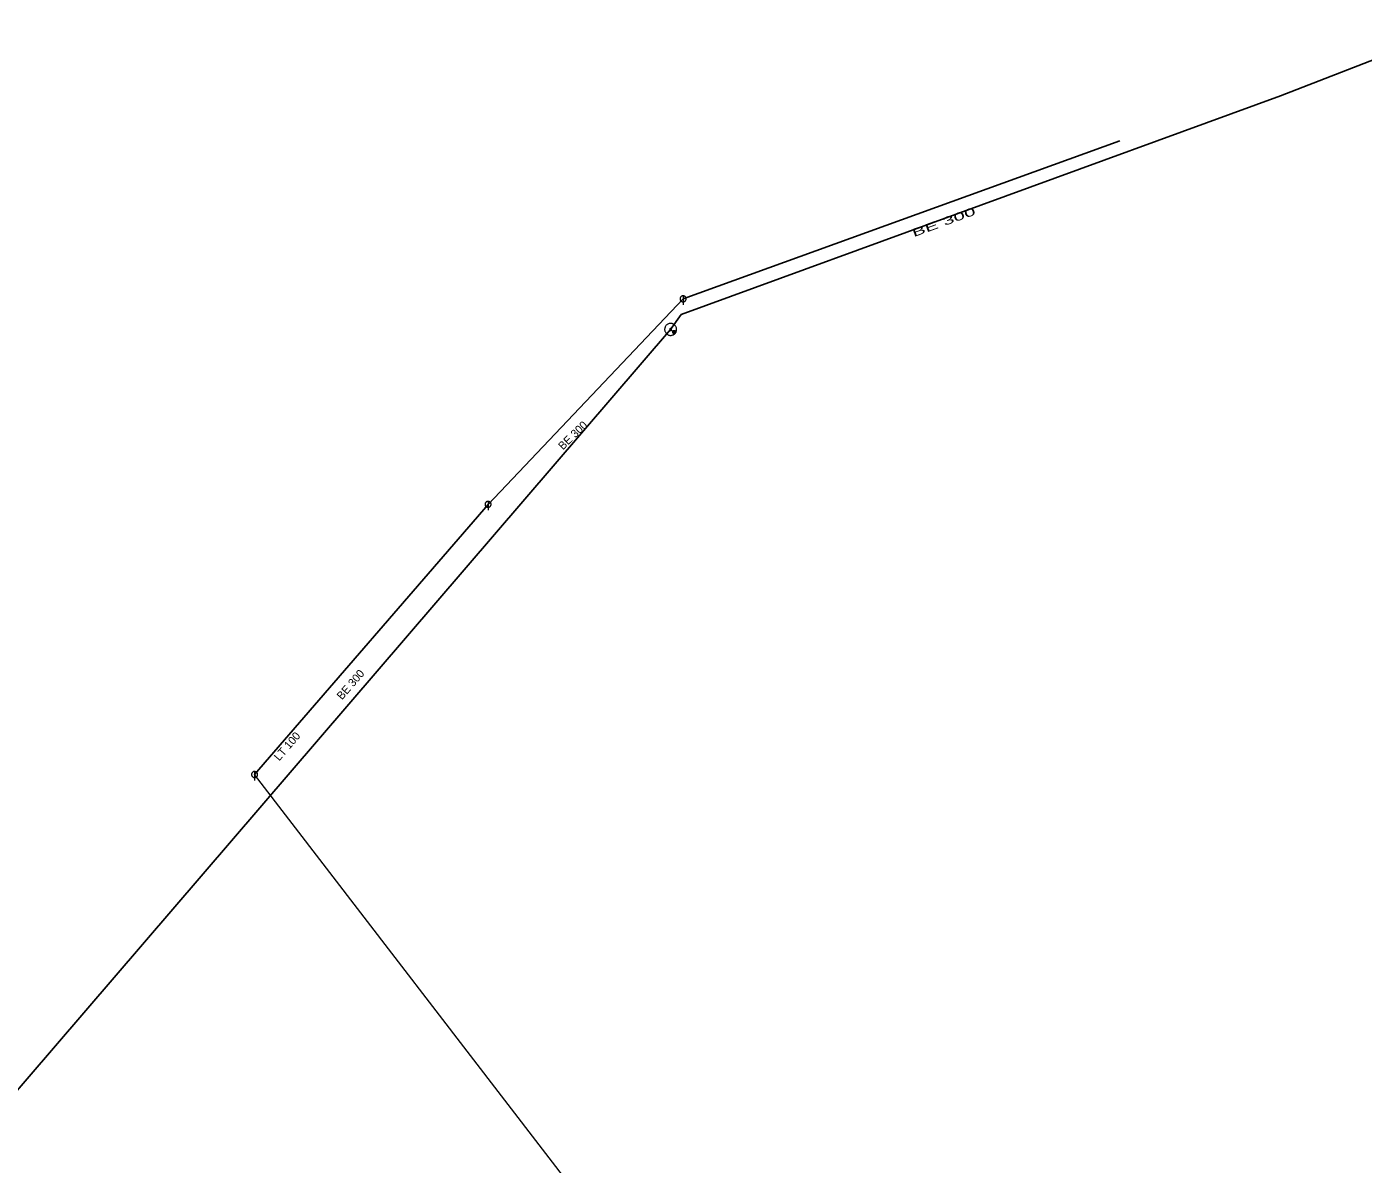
# Model space of a CAD drawing. Extents: x -687515 to -686506, y -974029 to -973461.
# Drawn here: x -687277.4 to -687166.1, y -973560 to -973465.2 of the extents above; entities that cross this region are included whole.
import ezdxf
from ezdxf.enums import TextEntityAlignment as Align

# ---------------------------------------------------------------- set-up
doc = ezdxf.new("R2010")
doc.units = 0
doc.header["$LTSCALE"] = 0.27
for name, color, linetype, lineweight in [('1', 7, 'Continuous', 13), ('11', 7, 'Continuous', 13), ('14', 7, 'Continuous', 25), ('17', 7, 'Continuous', 25), ('22', 7, 'Continuous', 13), ('47', 7, 'Continuous', 13), ('9', 7, 'Continuous', 13)]:
    doc.layers.add(name, color=color, linetype=linetype, lineweight=lineweight)

msp = doc.modelspace()

# ---------------------------------------------------------------- linework, layer by layer
at = {"layer": '11'}
msp.add_line((-687229.217, -973565.501), (-687258.444, -973527.487), dxfattribs=at)
at = {"layer": '14'}
msp.add_line((-687222.741, -973487.844), (-687186.354, -973474.678), dxfattribs=at)
at = {"layer": '14', "lineweight": 13}
msp.add_line((-687223.779, -973490.391), (-687223.489, -973490.623), dxfattribs=at)
at = {"layer": '14'}
msp.add_lwpolyline([(-687258.444, -973527.487), (-687238.992, -973504.972), (-687222.741, -973487.844)], dxfattribs=at)
at = {"layer": '17'}
msp.add_line((-687223.779, -973490.391), (-687283.189, -973559.579), dxfattribs=at)
msp.add_lwpolyline([(-687157.299, -973465.166), (-687162.314, -973466.789), (-687172.973, -973470.914), (-687222.892, -973489.136), (-687223.779, -973490.391)], dxfattribs=at)
at = {"layer": '22'}
for p, q in [((-687222.74, -973487.592), (-687222.741, -973488.336)), ((-687238.991, -973504.72), (-687238.992, -973505.463)), ((-687258.443, -973527.235), (-687258.444, -973527.978))]:
    msp.add_line(p, q, dxfattribs=at)
for points in [[(-687222.489, -973487.844), (-687222.49, -973487.818), (-687222.494, -973487.792), (-687222.5, -973487.766), (-687222.51, -973487.742), (-687222.522, -973487.718), (-687222.536, -973487.696), (-687222.553, -973487.675), (-687222.571, -973487.657), (-687222.592, -973487.64), (-687222.614, -973487.626), (-687222.638, -973487.614), (-687222.662, -973487.604), (-687222.688, -973487.598), (-687222.714, -973487.594), (-687222.74, -973487.592), (-687222.766, -973487.593), (-687222.792, -973487.597), (-687222.818, -973487.603), (-687222.843, -973487.613), (-687222.866, -973487.625), (-687222.888, -973487.639), (-687222.909, -973487.656), (-687222.927, -973487.674), (-687222.944, -973487.695), (-687222.958, -973487.717), (-687222.97, -973487.741), (-687222.98, -973487.765), (-687222.987, -973487.791), (-687222.991, -973487.817), (-687222.993, -973487.843), (-687222.992, -973487.869), (-687222.988, -973487.895), (-687222.981, -973487.921), (-687222.971, -973487.946), (-687222.959, -973487.969), (-687222.945, -973487.991), (-687222.928, -973488.012), (-687222.91, -973488.03), (-687222.889, -973488.047), (-687222.867, -973488.061), (-687222.844, -973488.073), (-687222.819, -973488.083), (-687222.793, -973488.09), (-687222.767, -973488.094), (-687222.741, -973488.096), (-687222.715, -973488.095), (-687222.689, -973488.091), (-687222.663, -973488.084), (-687222.639, -973488.074), (-687222.615, -973488.062), (-687222.593, -973488.048), (-687222.572, -973488.031), (-687222.554, -973488.013), (-687222.537, -973487.992), (-687222.523, -973487.97), (-687222.511, -973487.947), (-687222.501, -973487.922), (-687222.495, -973487.896), (-687222.491, -973487.87)], [(-687238.74, -973504.972), (-687238.741, -973504.946), (-687238.745, -973504.92), (-687238.751, -973504.894), (-687238.761, -973504.87), (-687238.773, -973504.846), (-687238.787, -973504.824), (-687238.804, -973504.803), (-687238.822, -973504.785), (-687238.843, -973504.768), (-687238.865, -973504.754), (-687238.889, -973504.742), (-687238.913, -973504.732), (-687238.939, -973504.726), (-687238.965, -973504.722), (-687238.991, -973504.72), (-687239.017, -973504.721), (-687239.043, -973504.725), (-687239.069, -973504.731), (-687239.094, -973504.741), (-687239.117, -973504.753), (-687239.139, -973504.767), (-687239.16, -973504.784), (-687239.178, -973504.802), (-687239.195, -973504.823), (-687239.209, -973504.845), (-687239.221, -973504.869), (-687239.231, -973504.893), (-687239.238, -973504.919), (-687239.242, -973504.945), (-687239.244, -973504.971), (-687239.243, -973504.997), (-687239.239, -973505.023), (-687239.232, -973505.049), (-687239.222, -973505.074), (-687239.21, -973505.097), (-687239.196, -973505.119), (-687239.179, -973505.14), (-687239.161, -973505.158), (-687239.14, -973505.175), (-687239.118, -973505.189), (-687239.095, -973505.201), (-687239.07, -973505.211), (-687239.044, -973505.218), (-687239.018, -973505.222), (-687238.992, -973505.223), (-687238.966, -973505.223), (-687238.94, -973505.219), (-687238.914, -973505.212), (-687238.89, -973505.202), (-687238.866, -973505.19), (-687238.844, -973505.176), (-687238.823, -973505.159), (-687238.805, -973505.141), (-687238.788, -973505.12), (-687238.774, -973505.098), (-687238.762, -973505.075), (-687238.752, -973505.05), (-687238.746, -973505.024), (-687238.742, -973504.998)], [(-687258.192, -973527.487), (-687258.193, -973527.461), (-687258.197, -973527.435), (-687258.203, -973527.409), (-687258.213, -973527.385), (-687258.225, -973527.361), (-687258.239, -973527.339), (-687258.256, -973527.318), (-687258.274, -973527.3), (-687258.295, -973527.283), (-687258.317, -973527.269), (-687258.341, -973527.257), (-687258.365, -973527.247), (-687258.391, -973527.241), (-687258.417, -973527.237), (-687258.443, -973527.235), (-687258.469, -973527.236), (-687258.495, -973527.24), (-687258.521, -973527.246), (-687258.546, -973527.256), (-687258.569, -973527.268), (-687258.591, -973527.282), (-687258.612, -973527.299), (-687258.63, -973527.317), (-687258.647, -973527.338), (-687258.661, -973527.36), (-687258.673, -973527.384), (-687258.683, -973527.408), (-687258.69, -973527.434), (-687258.694, -973527.46), (-687258.696, -973527.486), (-687258.695, -973527.512), (-687258.691, -973527.538), (-687258.684, -973527.564), (-687258.674, -973527.589), (-687258.662, -973527.612), (-687258.648, -973527.634), (-687258.631, -973527.655), (-687258.613, -973527.673), (-687258.592, -973527.69), (-687258.57, -973527.704), (-687258.547, -973527.716), (-687258.522, -973527.726), (-687258.496, -973527.733), (-687258.47, -973527.737), (-687258.444, -973527.739), (-687258.418, -973527.738), (-687258.392, -973527.734), (-687258.366, -973527.727), (-687258.342, -973527.717), (-687258.318, -973527.705), (-687258.296, -973527.691), (-687258.275, -973527.674), (-687258.257, -973527.656), (-687258.24, -973527.635), (-687258.226, -973527.613), (-687258.214, -973527.59), (-687258.204, -973527.565), (-687258.198, -973527.539), (-687258.194, -973527.513)]]:
    msp.add_lwpolyline(points, close=True, dxfattribs=at)
at = {"layer": '47'}
for points in [[(-687223.47, -973489.997), (-687223.513, -973489.967), (-687223.559, -973489.942), (-687223.607, -973489.922), (-687223.656, -973489.906), (-687223.708, -973489.895), (-687223.761, -973489.891), (-687223.812, -973489.892), (-687223.864, -973489.899), (-687223.915, -973489.91), (-687223.965, -973489.927), (-687224.013, -973489.949), (-687224.057, -973489.976), (-687224.099, -973490.007), (-687224.138, -973490.043), (-687224.172, -973490.082), (-687224.202, -973490.125), (-687224.227, -973490.171), (-687224.248, -973490.219), (-687224.263, -973490.268), (-687224.274, -973490.32), (-687224.278, -973490.373), (-687224.277, -973490.425), (-687224.271, -973490.477), (-687224.26, -973490.528), (-687224.242, -973490.577), (-687224.22, -973490.625), (-687224.193, -973490.67), (-687224.162, -973490.711), (-687224.126, -973490.75), (-687224.087, -973490.784), (-687224.044, -973490.814), (-687223.998, -973490.839), (-687223.95, -973490.861), (-687223.901, -973490.875), (-687223.849, -973490.886), (-687223.797, -973490.891), (-687223.744, -973490.89), (-687223.692, -973490.884), (-687223.641, -973490.872), (-687223.592, -973490.854), (-687223.544, -973490.832), (-687223.5, -973490.806), (-687223.458, -973490.774), (-687223.419, -973490.738), (-687223.385, -973490.699), (-687223.355, -973490.656), (-687223.33, -973490.61), (-687223.309, -973490.563), (-687223.294, -973490.513), (-687223.283, -973490.461), (-687223.278, -973490.409), (-687223.28, -973490.357), (-687223.286, -973490.305), (-687223.298, -973490.254), (-687223.315, -973490.204), (-687223.337, -973490.156), (-687223.363, -973490.112), (-687223.395, -973490.07), (-687223.431, -973490.031)], [(-687223.728, -973490.326), (-687223.735, -973490.32), (-687223.743, -973490.317), (-687223.75, -973490.314), (-687223.758, -973490.311), (-687223.767, -973490.309), (-687223.776, -973490.309), (-687223.784, -973490.309), (-687223.793, -973490.31), (-687223.801, -973490.312), (-687223.809, -973490.314), (-687223.817, -973490.318), (-687223.824, -973490.323), (-687223.831, -973490.328), (-687223.837, -973490.333), (-687223.843, -973490.34), (-687223.849, -973490.347), (-687223.852, -973490.355), (-687223.855, -973490.362), (-687223.858, -973490.37), (-687223.86, -973490.379), (-687223.86, -973490.388), (-687223.86, -973490.396), (-687223.859, -973490.405), (-687223.858, -973490.414), (-687223.855, -973490.421), (-687223.851, -973490.429), (-687223.846, -973490.436), (-687223.841, -973490.443), (-687223.836, -973490.449), (-687223.829, -973490.455), (-687223.822, -973490.461), (-687223.814, -973490.464), (-687223.807, -973490.467), (-687223.799, -973490.47), (-687223.79, -973490.472), (-687223.782, -973490.473), (-687223.773, -973490.472), (-687223.764, -973490.471), (-687223.755, -973490.47), (-687223.748, -973490.467), (-687223.74, -973490.463), (-687223.733, -973490.458), (-687223.726, -973490.453), (-687223.72, -973490.448), (-687223.714, -973490.441), (-687223.708, -973490.434), (-687223.705, -973490.426), (-687223.702, -973490.419), (-687223.699, -973490.411), (-687223.697, -973490.402), (-687223.696, -973490.394), (-687223.697, -973490.385), (-687223.698, -973490.376), (-687223.7, -973490.368), (-687223.702, -973490.36), (-687223.706, -973490.352), (-687223.711, -973490.345), (-687223.716, -973490.338), (-687223.721, -973490.332)]]:
    msp.add_lwpolyline(points, close=True, dxfattribs=at)
at = {"layer": '9'}
for points in [[(-687223.362, -973490.623), (-687223.364, -973490.61), (-687223.365, -973490.597), (-687223.369, -973490.584), (-687223.374, -973490.572), (-687223.379, -973490.56), (-687223.387, -973490.549), (-687223.394, -973490.539), (-687223.404, -973490.529), (-687223.414, -973490.521), (-687223.426, -973490.514), (-687223.438, -973490.508), (-687223.45, -973490.503), (-687223.463, -973490.5), (-687223.475, -973490.498), (-687223.489, -973490.497), (-687223.502, -973490.498), (-687223.514, -973490.5), (-687223.527, -973490.503), (-687223.539, -973490.508), (-687223.551, -973490.514), (-687223.563, -973490.521), (-687223.573, -973490.529), (-687223.583, -973490.539), (-687223.59, -973490.549), (-687223.598, -973490.56), (-687223.603, -973490.572), (-687223.608, -973490.584), (-687223.612, -973490.597), (-687223.614, -973490.61), (-687223.615, -973490.623), (-687223.614, -973490.636), (-687223.612, -973490.649), (-687223.608, -973490.662), (-687223.603, -973490.674), (-687223.598, -973490.686), (-687223.59, -973490.697), (-687223.583, -973490.707), (-687223.573, -973490.717), (-687223.563, -973490.725), (-687223.551, -973490.732), (-687223.539, -973490.738), (-687223.527, -973490.743), (-687223.514, -973490.746), (-687223.502, -973490.748), (-687223.489, -973490.749), (-687223.475, -973490.748), (-687223.463, -973490.746), (-687223.45, -973490.743), (-687223.438, -973490.738), (-687223.426, -973490.732), (-687223.414, -973490.725), (-687223.404, -973490.717), (-687223.394, -973490.707), (-687223.387, -973490.697), (-687223.379, -973490.686), (-687223.374, -973490.674), (-687223.369, -973490.662), (-687223.365, -973490.649), (-687223.364, -973490.636)], [(-687223.382, -973490.623), (-687223.382, -973490.612), (-687223.384, -973490.601), (-687223.387, -973490.59), (-687223.392, -973490.58), (-687223.397, -973490.57), (-687223.402, -973490.561), (-687223.409, -973490.552), (-687223.418, -973490.544), (-687223.426, -973490.537), (-687223.436, -973490.531), (-687223.446, -973490.526), (-687223.455, -973490.522), (-687223.467, -973490.519), (-687223.477, -973490.517), (-687223.489, -973490.517), (-687223.5, -973490.517), (-687223.511, -973490.519), (-687223.522, -973490.522), (-687223.531, -973490.526), (-687223.541, -973490.531), (-687223.551, -973490.537), (-687223.559, -973490.544), (-687223.568, -973490.552), (-687223.575, -973490.561), (-687223.58, -973490.57), (-687223.585, -973490.58), (-687223.59, -973490.59), (-687223.593, -973490.601), (-687223.595, -973490.612), (-687223.595, -973490.623), (-687223.595, -973490.634), (-687223.593, -973490.645), (-687223.59, -973490.656), (-687223.585, -973490.666), (-687223.58, -973490.676), (-687223.575, -973490.685), (-687223.568, -973490.694), (-687223.559, -973490.702), (-687223.551, -973490.709), (-687223.541, -973490.715), (-687223.531, -973490.72), (-687223.522, -973490.724), (-687223.511, -973490.727), (-687223.5, -973490.729), (-687223.489, -973490.729), (-687223.477, -973490.729), (-687223.467, -973490.727), (-687223.455, -973490.724), (-687223.446, -973490.72), (-687223.436, -973490.715), (-687223.426, -973490.709), (-687223.418, -973490.702), (-687223.409, -973490.694), (-687223.402, -973490.685), (-687223.397, -973490.676), (-687223.392, -973490.666), (-687223.387, -973490.656), (-687223.384, -973490.645), (-687223.382, -973490.634)], [(-687223.401, -973490.623), (-687223.402, -973490.614), (-687223.404, -973490.605), (-687223.406, -973490.596), (-687223.409, -973490.588), (-687223.414, -973490.58), (-687223.419, -973490.572), (-687223.424, -973490.565), (-687223.431, -973490.559), (-687223.438, -973490.553), (-687223.446, -973490.548), (-687223.453, -973490.544), (-687223.462, -973490.541), (-687223.47, -973490.538), (-687223.48, -973490.537), (-687223.489, -973490.536), (-687223.497, -973490.537), (-687223.507, -973490.538), (-687223.516, -973490.541), (-687223.524, -973490.544), (-687223.531, -973490.548), (-687223.539, -973490.553), (-687223.546, -973490.559), (-687223.553, -973490.565), (-687223.558, -973490.572), (-687223.563, -973490.58), (-687223.568, -973490.588), (-687223.571, -973490.596), (-687223.573, -973490.605), (-687223.575, -973490.614), (-687223.576, -973490.623), (-687223.575, -973490.632), (-687223.573, -973490.641), (-687223.571, -973490.65), (-687223.568, -973490.658), (-687223.563, -973490.666), (-687223.558, -973490.674), (-687223.553, -973490.681), (-687223.546, -973490.687), (-687223.539, -973490.693), (-687223.531, -973490.698), (-687223.524, -973490.702), (-687223.516, -973490.705), (-687223.507, -973490.708), (-687223.497, -973490.709), (-687223.489, -973490.71), (-687223.48, -973490.709), (-687223.47, -973490.708), (-687223.462, -973490.705), (-687223.453, -973490.702), (-687223.446, -973490.698), (-687223.438, -973490.693), (-687223.431, -973490.687), (-687223.424, -973490.681), (-687223.419, -973490.674), (-687223.414, -973490.666), (-687223.409, -973490.658), (-687223.406, -973490.65), (-687223.404, -973490.641), (-687223.402, -973490.632)], [(-687223.421, -973490.623), (-687223.421, -973490.616), (-687223.424, -973490.609), (-687223.424, -973490.602), (-687223.428, -973490.596), (-687223.431, -973490.59), (-687223.434, -973490.584), (-687223.438, -973490.578), (-687223.443, -973490.573), (-687223.45, -973490.569), (-687223.455, -973490.565), (-687223.462, -973490.562), (-687223.468, -973490.559), (-687223.475, -973490.558), (-687223.482, -973490.556), (-687223.489, -973490.556), (-687223.495, -973490.556), (-687223.502, -973490.558), (-687223.509, -973490.559), (-687223.516, -973490.562), (-687223.522, -973490.565), (-687223.527, -973490.569), (-687223.534, -973490.573), (-687223.539, -973490.578), (-687223.543, -973490.584), (-687223.546, -973490.59), (-687223.549, -973490.596), (-687223.553, -973490.602), (-687223.554, -973490.609), (-687223.556, -973490.616), (-687223.556, -973490.623), (-687223.556, -973490.63), (-687223.554, -973490.637), (-687223.553, -973490.644), (-687223.549, -973490.65), (-687223.546, -973490.657), (-687223.543, -973490.662), (-687223.539, -973490.668), (-687223.534, -973490.673), (-687223.527, -973490.677), (-687223.522, -973490.681), (-687223.516, -973490.684), (-687223.509, -973490.687), (-687223.502, -973490.689), (-687223.495, -973490.69), (-687223.489, -973490.69), (-687223.482, -973490.69), (-687223.475, -973490.689), (-687223.468, -973490.687), (-687223.462, -973490.684), (-687223.455, -973490.681), (-687223.45, -973490.677), (-687223.443, -973490.673), (-687223.438, -973490.668), (-687223.434, -973490.662), (-687223.431, -973490.657), (-687223.428, -973490.65), (-687223.424, -973490.644), (-687223.424, -973490.637), (-687223.421, -973490.63)], [(-687223.441, -973490.623), (-687223.441, -973490.618), (-687223.443, -973490.613), (-687223.443, -973490.608), (-687223.446, -973490.604), (-687223.448, -973490.599), (-687223.451, -973490.595), (-687223.453, -973490.592), (-687223.458, -973490.588), (-687223.46, -973490.585), (-687223.465, -973490.582), (-687223.47, -973490.58), (-687223.473, -973490.578), (-687223.478, -973490.577), (-687223.483, -973490.576), (-687223.489, -973490.576), (-687223.494, -973490.576), (-687223.499, -973490.577), (-687223.504, -973490.578), (-687223.507, -973490.58), (-687223.512, -973490.582), (-687223.517, -973490.585), (-687223.521, -973490.588), (-687223.524, -973490.592), (-687223.526, -973490.595), (-687223.529, -973490.599), (-687223.531, -973490.604), (-687223.534, -973490.608), (-687223.534, -973490.613), (-687223.536, -973490.618), (-687223.536, -973490.623), (-687223.536, -973490.628), (-687223.534, -973490.633), (-687223.534, -973490.638), (-687223.531, -973490.642), (-687223.529, -973490.647), (-687223.526, -973490.651), (-687223.524, -973490.655), (-687223.521, -973490.658), (-687223.517, -973490.661), (-687223.512, -973490.664), (-687223.507, -973490.666), (-687223.504, -973490.668), (-687223.499, -973490.669), (-687223.494, -973490.67), (-687223.489, -973490.67), (-687223.483, -973490.67), (-687223.478, -973490.669), (-687223.473, -973490.668), (-687223.47, -973490.666), (-687223.465, -973490.664), (-687223.46, -973490.661), (-687223.458, -973490.658), (-687223.453, -973490.655), (-687223.451, -973490.651), (-687223.448, -973490.647), (-687223.446, -973490.642), (-687223.443, -973490.638), (-687223.443, -973490.633), (-687223.441, -973490.628)], [(-687223.462, -973490.623), (-687223.462, -973490.62), (-687223.462, -973490.617), (-687223.463, -973490.615), (-687223.463, -973490.612), (-687223.465, -973490.609), (-687223.467, -973490.607), (-687223.468, -973490.605), (-687223.47, -973490.603), (-687223.473, -973490.601), (-687223.475, -973490.599), (-687223.477, -973490.598), (-687223.48, -973490.597), (-687223.482, -973490.596), (-687223.485, -973490.596), (-687223.489, -973490.596), (-687223.492, -973490.596), (-687223.495, -973490.596), (-687223.497, -973490.597), (-687223.5, -973490.598), (-687223.502, -973490.599), (-687223.504, -973490.601), (-687223.507, -973490.603), (-687223.509, -973490.605), (-687223.511, -973490.607), (-687223.512, -973490.609), (-687223.514, -973490.612), (-687223.514, -973490.615), (-687223.516, -973490.617), (-687223.516, -973490.62), (-687223.517, -973490.623), (-687223.516, -973490.626), (-687223.516, -973490.629), (-687223.514, -973490.632), (-687223.514, -973490.634), (-687223.512, -973490.637), (-687223.511, -973490.639), (-687223.509, -973490.642), (-687223.507, -973490.644), (-687223.504, -973490.645), (-687223.502, -973490.647), (-687223.5, -973490.648), (-687223.497, -973490.649), (-687223.495, -973490.65), (-687223.492, -973490.65), (-687223.489, -973490.651), (-687223.485, -973490.65), (-687223.482, -973490.65), (-687223.48, -973490.649), (-687223.477, -973490.648), (-687223.475, -973490.647), (-687223.473, -973490.645), (-687223.47, -973490.644), (-687223.468, -973490.642), (-687223.467, -973490.639), (-687223.465, -973490.637), (-687223.463, -973490.634), (-687223.463, -973490.632), (-687223.462, -973490.629), (-687223.462, -973490.626)], [(-687223.48, -973490.623), (-687223.48, -973490.622), (-687223.48, -973490.621), (-687223.482, -973490.621), (-687223.482, -973490.62), (-687223.482, -973490.619), (-687223.482, -973490.618), (-687223.482, -973490.618), (-687223.483, -973490.617), (-687223.483, -973490.617), (-687223.485, -973490.616), (-687223.485, -973490.616), (-687223.487, -973490.616), (-687223.487, -973490.615), (-687223.487, -973490.615), (-687223.489, -973490.615), (-687223.49, -973490.615), (-687223.49, -973490.615), (-687223.49, -973490.616), (-687223.492, -973490.616), (-687223.492, -973490.616), (-687223.494, -973490.617), (-687223.494, -973490.617), (-687223.495, -973490.618), (-687223.495, -973490.618), (-687223.495, -973490.619), (-687223.495, -973490.62), (-687223.497, -973490.621), (-687223.497, -973490.621), (-687223.497, -973490.622), (-687223.497, -973490.623), (-687223.497, -973490.624), (-687223.497, -973490.625), (-687223.497, -973490.625), (-687223.495, -973490.626), (-687223.495, -973490.627), (-687223.495, -973490.628), (-687223.495, -973490.628), (-687223.494, -973490.629), (-687223.494, -973490.629), (-687223.492, -973490.63), (-687223.492, -973490.63), (-687223.49, -973490.631), (-687223.49, -973490.631), (-687223.49, -973490.631), (-687223.489, -973490.631), (-687223.487, -973490.631), (-687223.487, -973490.631), (-687223.487, -973490.631), (-687223.485, -973490.63), (-687223.485, -973490.63), (-687223.483, -973490.629), (-687223.483, -973490.629), (-687223.482, -973490.628), (-687223.482, -973490.628), (-687223.482, -973490.627), (-687223.482, -973490.626), (-687223.482, -973490.625), (-687223.48, -973490.625), (-687223.48, -973490.624)]]:
    msp.add_lwpolyline(points, close=True, dxfattribs=at)

# ---------------------------------------------------------------- texts
at = {"layer": '1', "width": 1.9}
msp.add_text('BE 300', height=0.6667, rotation=20, dxfattribs=at).set_placement((-687200.914, -973481.752), align=Align.CENTER)
at = {"layer": '1'}
for s, rotation, p in [('BE 300', 44, (-687231.703, -973499.458)), ('BE 300', 49, (-687250.201, -973520.203)), ('LT 100', 49, (-687255.484, -973525.348))]:
    msp.add_text(s, height=0.6667, rotation=rotation, dxfattribs=at).set_placement(p, align=Align.CENTER)

doc.saveas('drawing.dxf')
